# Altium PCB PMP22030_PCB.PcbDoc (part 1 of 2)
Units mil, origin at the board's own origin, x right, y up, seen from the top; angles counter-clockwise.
Board outline 4950 x 3450 mil, 4 copper layers (Top Layer, Signal Layer 1, Signal Layer 2, Bottom Layer), stack 55.6 mil thick; 125 components, 59 nets, 280 pads, 156 vias.
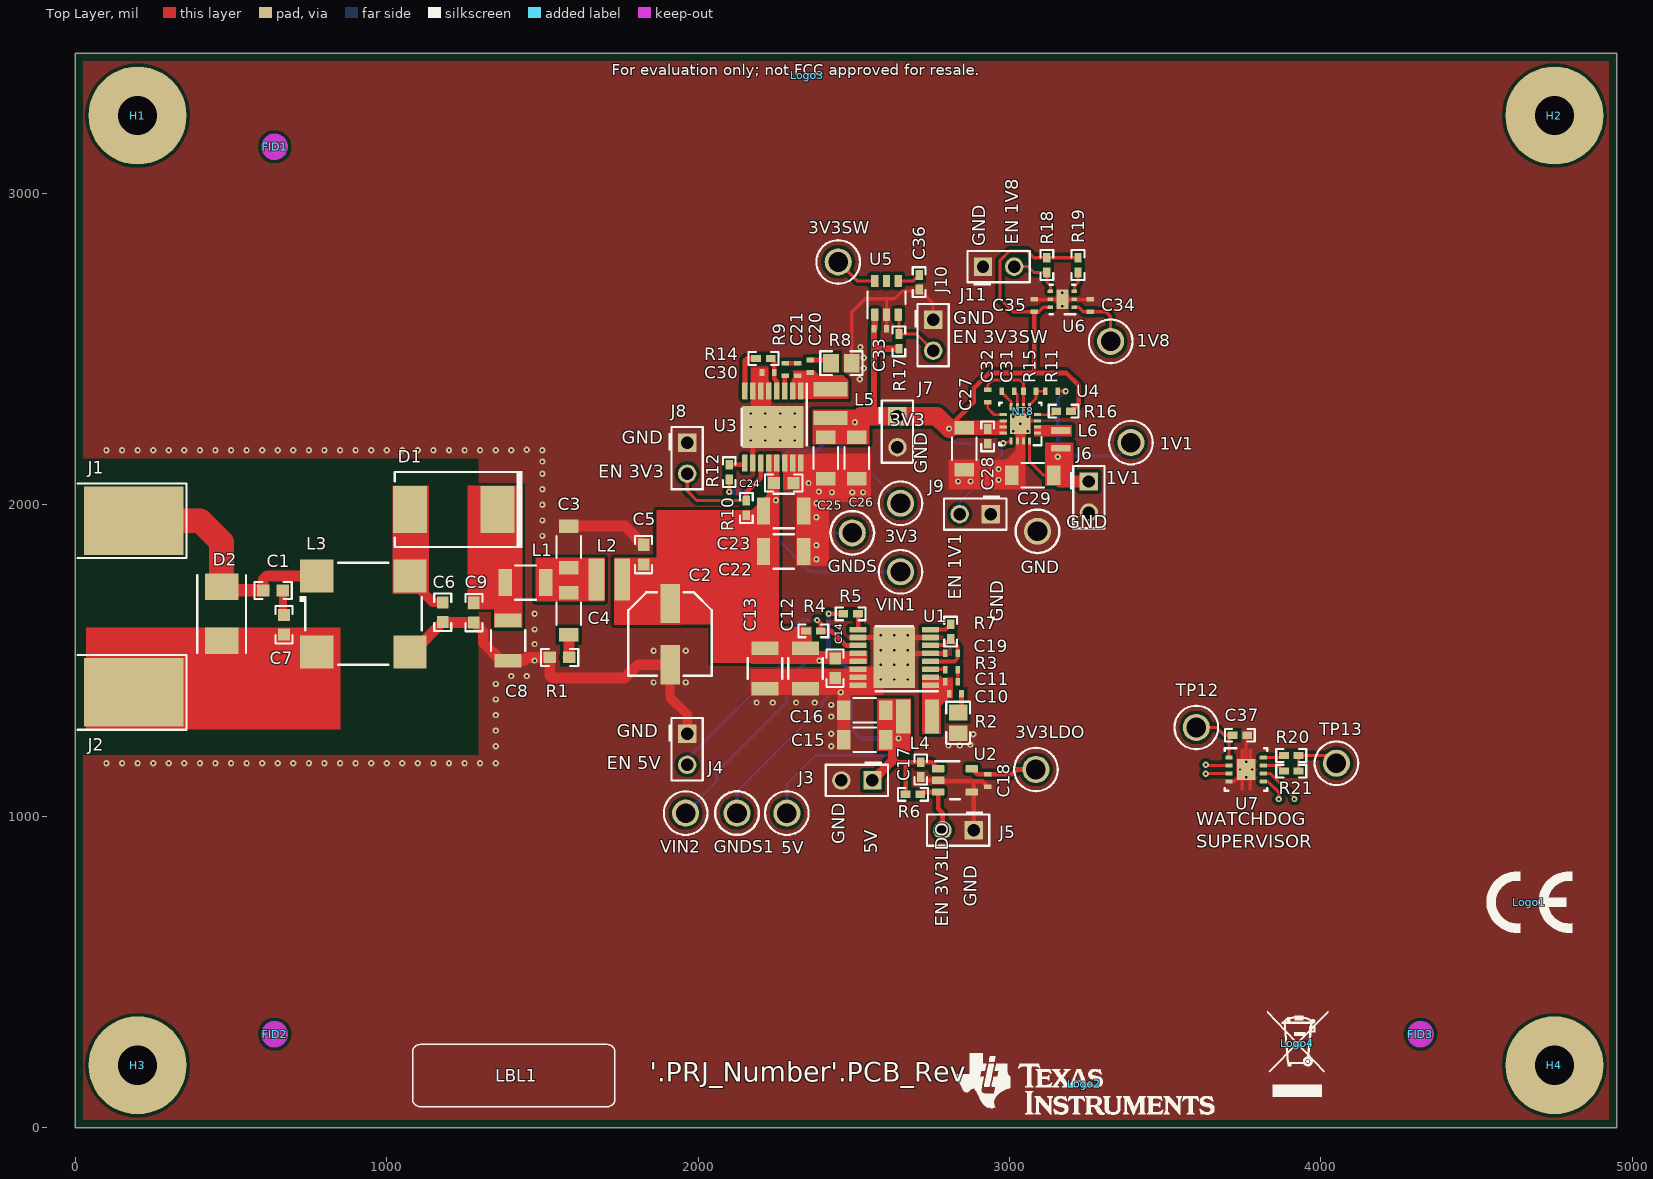
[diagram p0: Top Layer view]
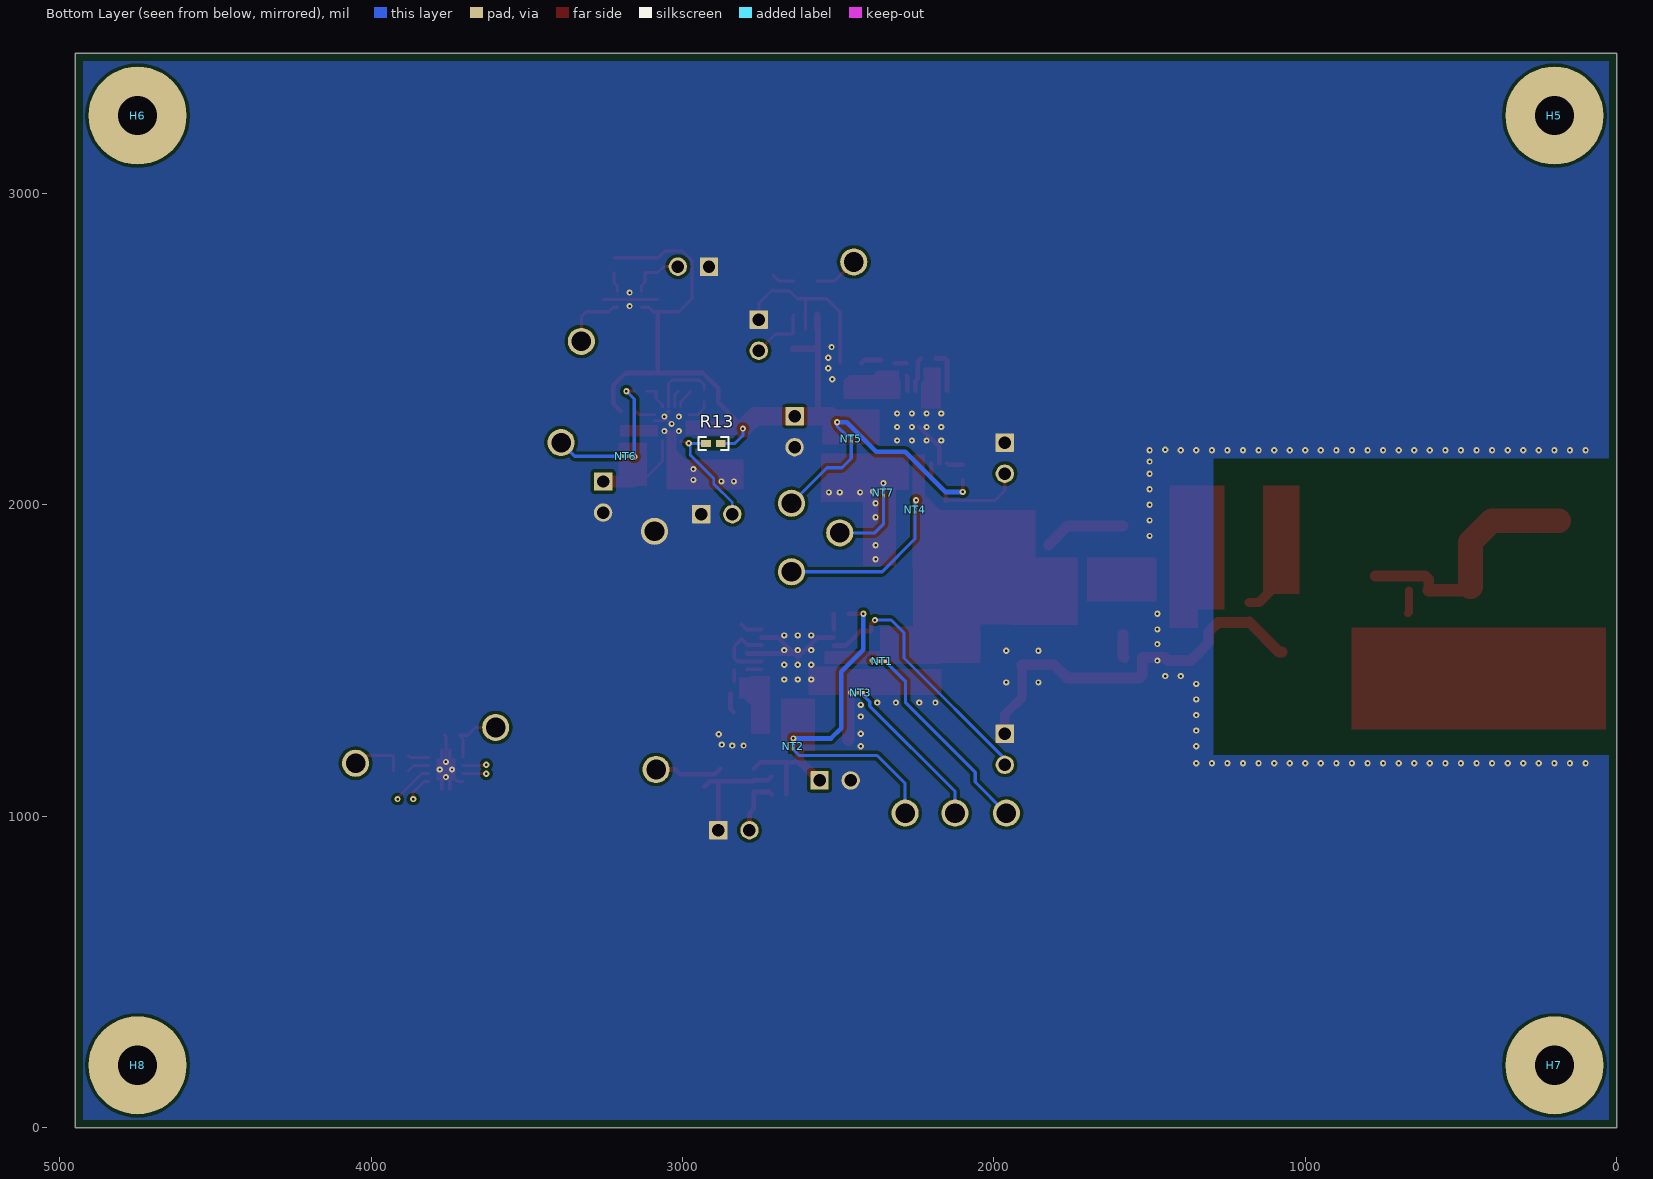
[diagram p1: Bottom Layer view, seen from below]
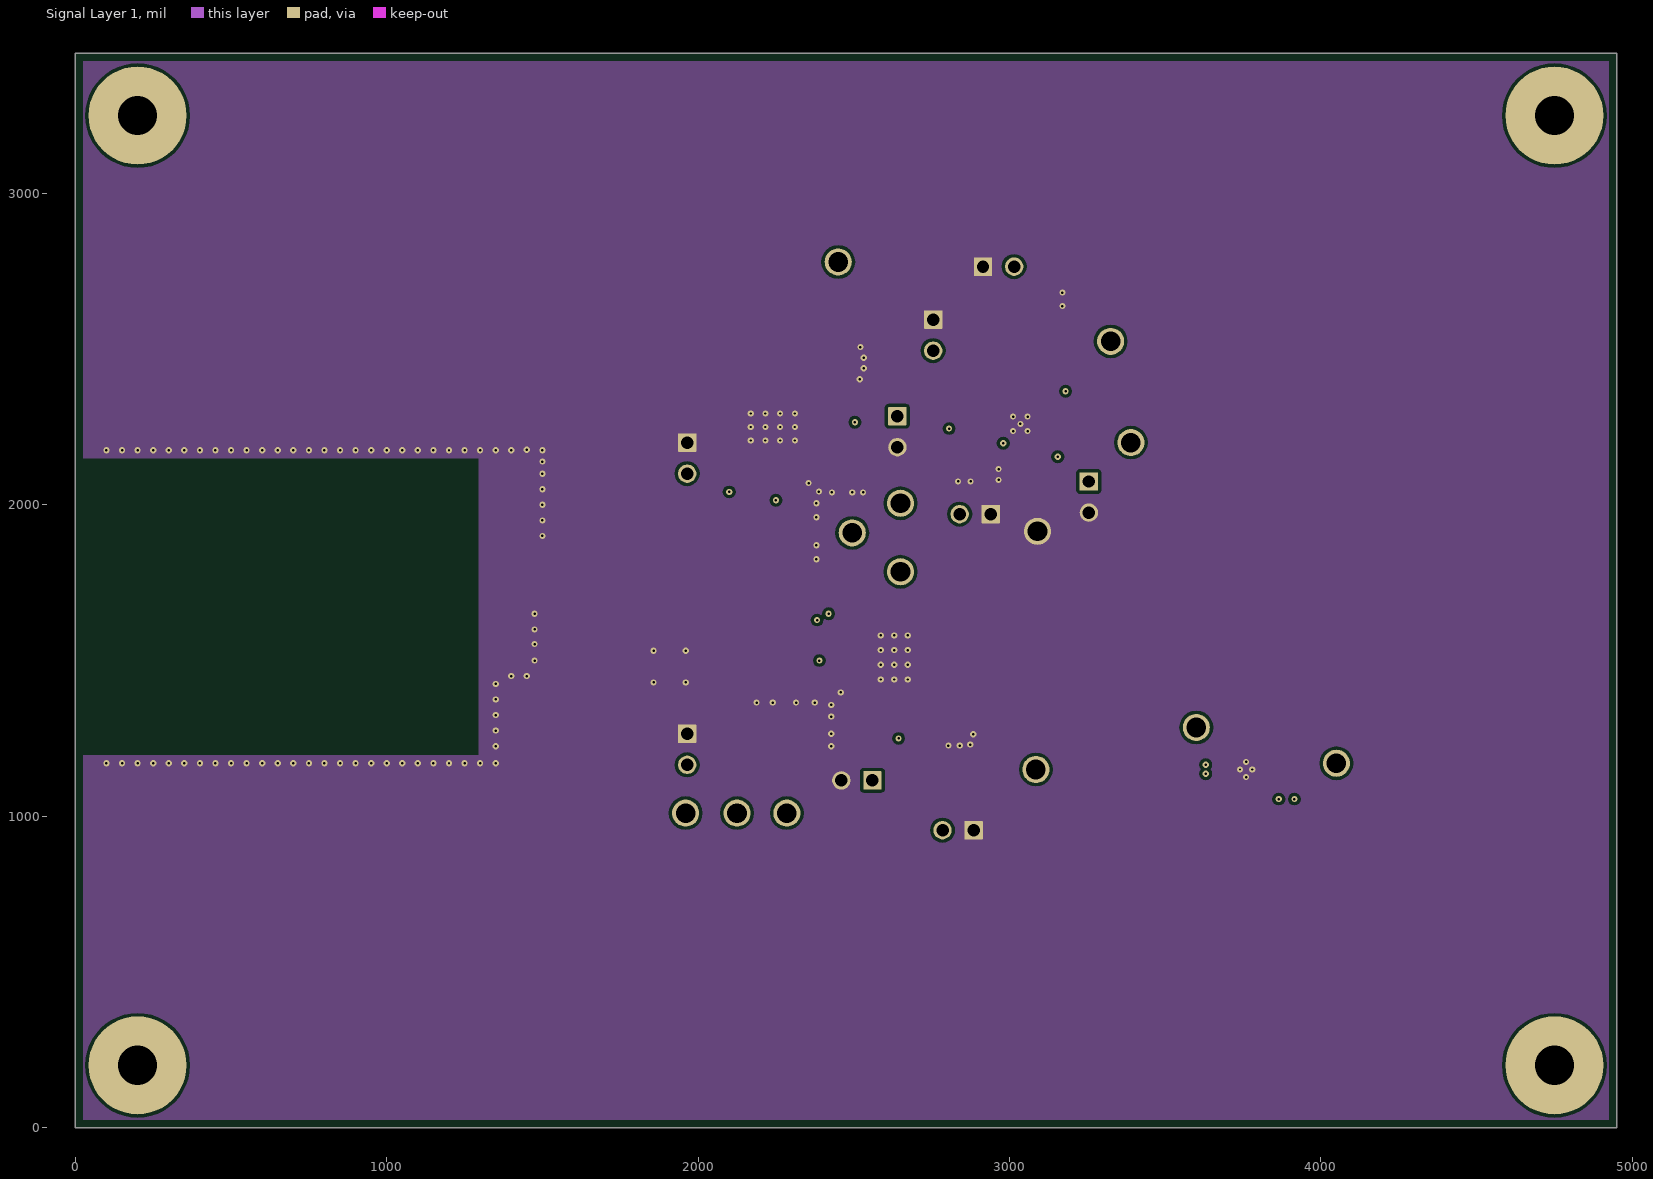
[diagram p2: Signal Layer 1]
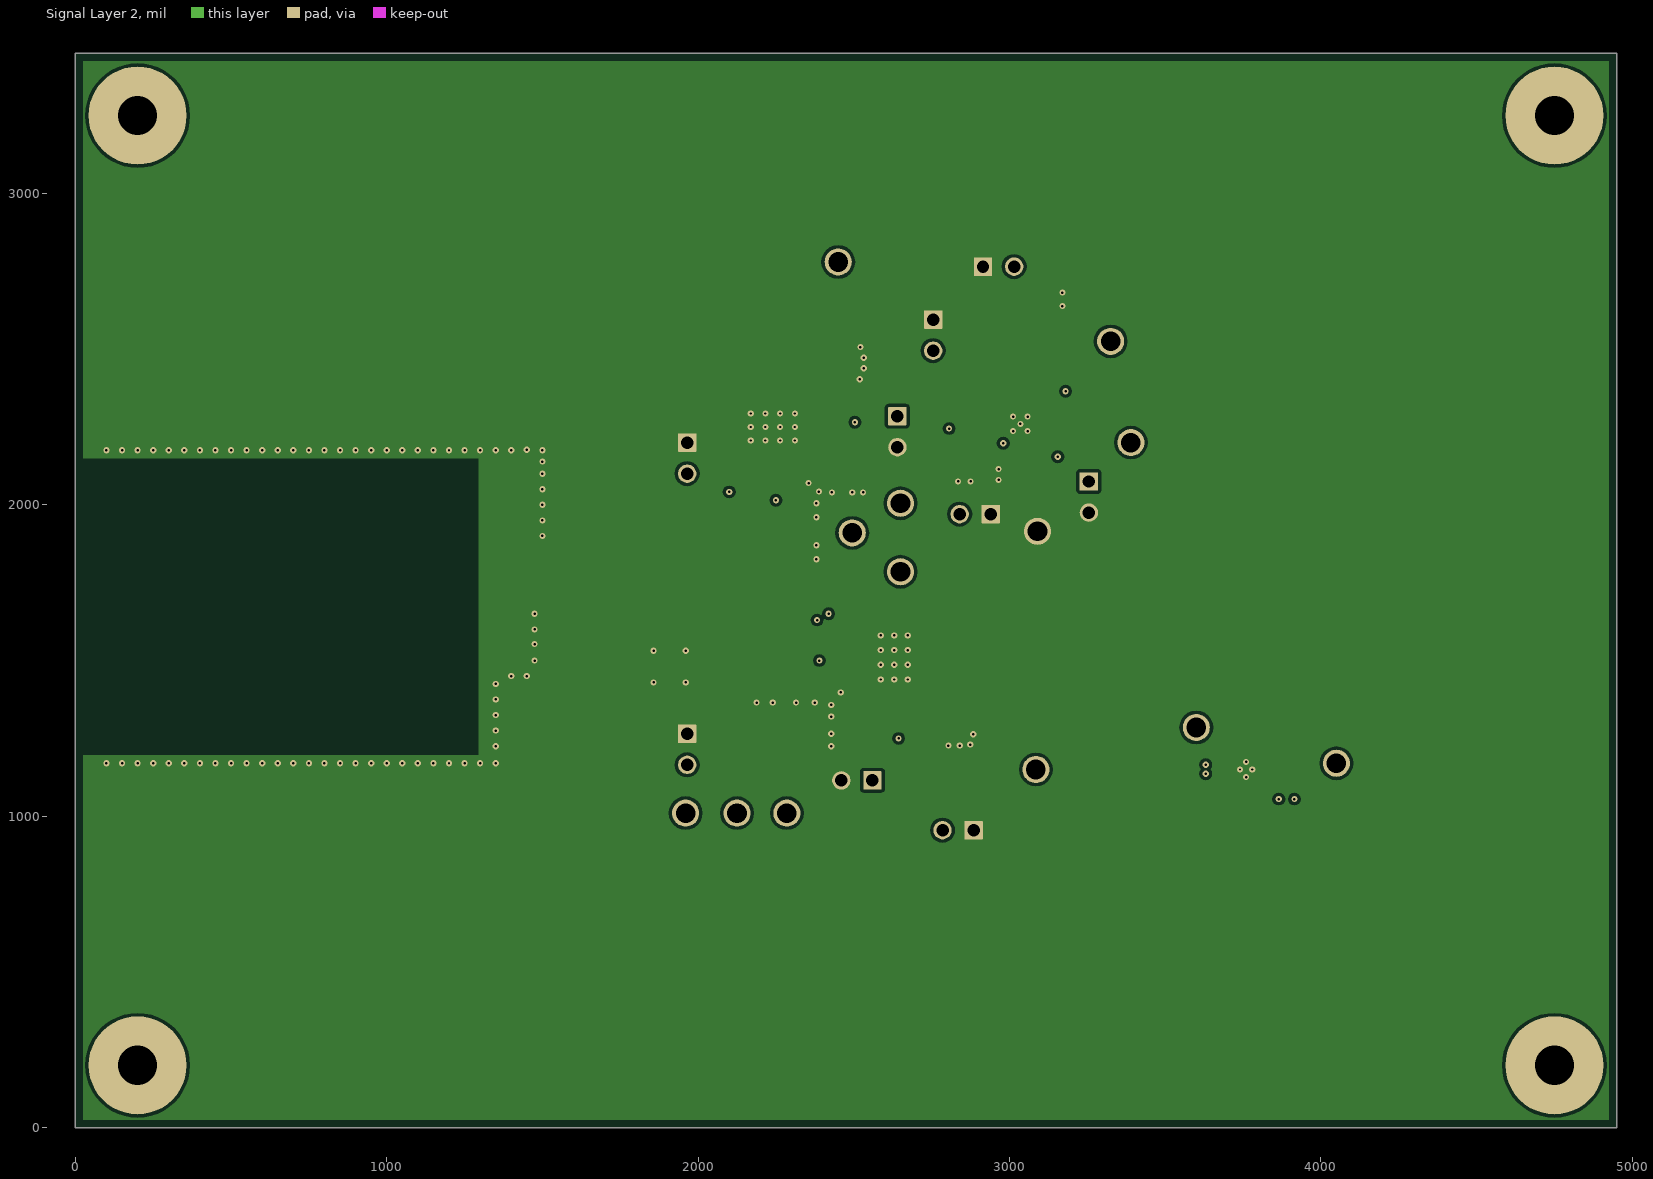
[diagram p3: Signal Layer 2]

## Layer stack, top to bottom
Top Solder: solder mask 0.4, Solder Resist, Dk 3.5
Top Layer: signal copper 1.4
Dielectric 2: prepreg 5, Dk 4.2
Signal Layer 1: signal copper 1.4
Dielectric1: core 40, FR-4, Dk 4.8
Signal Layer 2: signal copper 1.4
Dielectric 3: prepreg 5, Dk 4.2
Bottom Layer: signal copper 1.4
Bottom Solder: solder mask 0.4, Solder Resist, Dk 3.5

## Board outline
0,0 4950,0 4950,3450 0,3450

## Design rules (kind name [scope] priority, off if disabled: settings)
AcuteAngle [All] p1: minimum=4.50000000000000E+0001 checktracksonly=FALSE
AssemblyTestPointUsage [All] p1: valid=2
BoardOutlineClearance BoardOutlineClearance_MountingHoles [OnCopper and InComponentClass('Mounting Holes')] p1: gap=39.37 ignorepadtopadclearanceinfootprint=FALSE
BoardOutlineClearance BoardOutlineClearance_Poly [OnCopper and IsPoly] p2: gap=25 ignorepadtopadclearanceinfootprint=FALSE
BoardOutlineClearance [OnCopper and Not InComponentClass('Logo') and not InComponentClass('FiducialMark') and not InRegion(1000,500,4000,800) and not InPoly] p3: gap=75 ignorepadtopadclearanceinfootprint=FALSE
Clearance Clearance_Keepouts [((IsTrack Or IsArc) And Not InPoly) And IsFree and IsKeepOut vs ((IsTrack Or IsArc) And Not InPoly) And IsFree and IsKeepOut] p1: gap=0 ignorepadtopadclearanceinfootprint=FALSE
Clearance Clearance_Poly [InPolygon] p2: gap=10 ignorepadtopadclearanceinfootprint=TRUE
Clearance Clearance_FiducialMark [IsKeepOut and InComponentClass('FiducialMark') vs IsPad and InComponentClass('FiducialMark')] p3: gap=0 ignorepadtopadclearanceinfootprint=FALSE
Clearance [All] p4: gap=7.87 ignorepadtopadclearanceinfootprint=TRUE
ComponentClearance ComponentClearance_MountingHoles_FiducialMarks [InComponentClass('Mounting Holes') vs InComponentClass('FiducialMark')] p1: gap=50 collisioncheckmode=3 verticalgap=10 showdistances=FALSE
ComponentClearance ComponentClearance_Shunt [InComponentClass('Header') vs InComponentClass('Shunt')] p2: gap=0 collisioncheckmode=3 verticalgap=0 showdistances=FALSE
ComponentClearance ComponentClearance_Logo [InComponentClass('Logo')] p3: gap=50 collisioncheckmode=3 verticalgap=10 showdistances=FALSE
ComponentClearance ComponentClearance_ScrewToNut [(HasFootprint('NY PMS 440 0025 PH')) vs (HasFootprint('Keystone_1902C'))] p4: gap=5 collisioncheckmode=3 verticalgap=10 showdistances=FALSE
ComponentClearance ComponentClearance_MountingHoles [InComponentClass('Mounting Holes')] p5: gap=250 collisioncheckmode=3 verticalgap=100000 showdistances=FALSE
ComponentClearance ComponentClearance_SmallPassives [HasFootprint('0201*') or HasFootprint('0402*') or HasFootprint('0508') or HasFootprint('0603*') or HasFootprint('0612') or HasFootprint('0805*') or HasFootprint('0815*') or HasFootprint('0830*') or HasFootprint('1206*') or HasFootprint('1210*') or HasFootprint('1808*') or HasFootprint('1812*') or HasFootprint('1825*') or HasFootprint('2010*') or HasFootprint('2220*') or HasFootprint('2225*') or HasFootprint('2512*') or HasFootprint('2728*') or HasFootprint('3518*') vs HasFootprint('0201*') or HasFootprint('0402*') or HasFootprint('0508') or HasFootprint('0603*') or HasFootprint('0612') or HasFootprint('0805*') or HasFootprint('0815*') or HasFootprint('0830*') or HasFootprint('1206*') or HasFootprint('1210*') or HasFootprint('1808*') or HasFootprint('1812*') or HasFootprint('1825*') or HasFootprint('2010*') or HasFootprint('2220*') or HasFootprint('2225*') or HasFootprint('2512*') or HasFootprint('2728*') or HasFootprint('3518*')] p6: gap=14.96 collisioncheckmode=3 verticalgap=10 showdistances=FALSE
ComponentClearance ComponentClearance_THtoSMT [IsThruComponent vs IsSMTComponent] p7: gap=40 collisioncheckmode=3 verticalgap=30 showdistances=FALSE
ComponentClearance ComponentClearance_THtoTH [IsThruComponent vs IsThruComponent] p8: gap=30 collisioncheckmode=3 verticalgap=30 showdistances=FALSE
ComponentClearance [All] p9: gap=30 collisioncheckmode=3 verticalgap=10 showdistances=FALSE
DiffPairsRouting [All] p1: maxlimit=100 minlimit=10 mostfreqgap=10 toplayer_minwidth=15 toplayer_maxwidth=15 toplayer_prefwidth=15 midlayer1_minwidth=15 midlayer1_maxwidth=15 midlayer1_prefwidth=15 midlayer2_minwidth=15 midlayer2_maxwidth=15 midlayer2_prefwidth=15 bottomlayer_minwidth=15 bottomlayer_maxwidth=15 bottomlayer_prefwidth=15 maxuncoupledlength=1000
FabricationTestPointUsage TestPointUsage [All] p1: valid=2 allowmultiple=FALSE
FabricationTestpoint Testpoint [All] p1: side=3 testpointundercomponent=TRUE minsize=40 maxsize=100 preferedsize=60 minholesize=0 maxholesize=40 preferedholesize=32 testpointgrid=1 allowsidetop=TRUE allowsidebottom=TRUE usegrid=TRUE gridtolerance=0.01
FanoutControl Fanout_LCC [IsLCC] p1: bgadir=Out bgaviamode=Centered fanoutstyle=Auto fanoutdirection=Alternating viagrid=1 // Fanout_LCC (Default Rule)
FanoutControl Fanout_BGA [IsBGA] p2: bgadir=Out bgaviamode=Centered fanoutstyle=Auto fanoutdirection=Alternating viagrid=1 // Fanout_BGA (Default Rule)
FanoutControl Fanout_Default [All] p4: bgadir=Out bgaviamode=Centered fanoutstyle=Auto fanoutdirection=Alternating viagrid=1 // Fanout_Default (Default Rule)
FanoutControl Fanout_Small [(CompPinCount < 5)] p5: bgadir=Out bgaviamode=Centered fanoutstyle=Auto fanoutdirection=OutThenIn viagrid=1 // Fanout_Small (Default Rule)
HoleSize [All] p1: absolutevalues=TRUE maxlimit=251 minlimit=7.87 maxpercent=80.000 minpercent=20.000
MinimumAnnularRing MinimumAnnularRing_ThermalPadVias [IsVia and InAnyComponent] p1: minimumring=5.91
MinimumAnnularRing [All] p2: minimumring=6
MinimumSolderMaskSliver MinimumSolderMaskSliver_Logo [InComponentClass('Logo') vs InComponentClass('Logo')] p1: minsoldermaskwidth=0.7
MinimumSolderMaskSliver [All] p2: minsoldermaskwidth=3.94
PlaneConnect [All] p1: planeconnectstyle=Relief reliefexpansion=10 reliefentries=4 reliefconductorwidth=10 reliefairgap=10
PolygonConnect [All] p1: connectstyle=Direct reliefconductorwidth=10 reliefentries=4 polygonreliefangle="90 Angle" airgapwidth=10
RoutingVias ThermalPadVias [IsVia and InAnyComponent] p1: holewidth=7.87 width=19.68 viastyle="Through Hole" minholewidth=7.87 minwidth=19.68 maxholewidth=12.99 maxwidth=23.62
RoutingVias [All] p2: holewidth=16 width=34 viastyle="Through Hole" minholewidth=7.87 minwidth=20 maxholewidth=40 maxwidth=65
SilkToBoardRegionClearance [Not ((IsComment or IsDesignator) And (Hide <> 'False')) and not InRegion(1000,500,4000,800)] p1:
SilkToSilkClearance SilkToSilkClearance_Pb-FreeLogo [(HasFootprint('Pb-Free_Overlay_Medium') OR HasFootprint('Pb-Free_Overlay_Small')) vs (HasFootprint('Pb-Free_Overlay_Medium') OR HasFootprint('Pb-Free_Overlay_Small'))] p1: silktosilkclearance=0
SilkToSilkClearance [All] p2: silktosilkclearance=3.94
SilkToSolderMaskClearance SilkToComponentPadClearance [(IsPad or IsFill or IsRegion) and InAnycomponent] p1: minsilkscreentomaskgap=5 clearancetoexposedcopper=TRUE
SilkToSolderMaskClearance "Silk to Solder Mask Opening" [All] p2: minsilkscreentomaskgap=3.94 clearancetoexposedcopper=FALSE
SolderMaskExpansion [All] p1: expansion=1.97
UnRoutedNet [All] p1: checkbadconnections=TRUE
Width [All] p1: maxlimit=100 minlimit=6 preferedwidth=10 checkconnectedcopper=TRUE
14 further rules are at their usual default settings.

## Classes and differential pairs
component class PMP22030_5V: 3V3LDO 5V C1 C2 C3 C4 C5 C6 C7 C8 C9 C10 C11 C12 C13 C14 C15 C16 C17 C18 C19 D1 D2 GNDS1 J1 J2 J3 J4 J5 L1 L2 L3 L4 NT1 NT2 NT3 R1 R2 R3 R4 R5 R6 R7 U1 U2 VIN2
component class PMP22030_3V3: 1V1 1V8 3V3 3V3SW C20 C21 C22 C23 C24 C25 C26 C27 C28 C29 C30 C31 C32 C33 C34 C35 C36 C37 GND GNDS J6 J7 J8 J9 J10 J11 L5 L6 NT4 NT5 NT6 NT7 NT8 R8 R9 R10 R11 R12 R13 R14 R15 R16 R17 R18 R19 R20 R21 TP12 TP13 U3 U4 U5 U6 U7 VIN1
component class Header: J3 J4 J5 J6 J7 J8 J9 J10 J11
component class "Mounting Holes": H1 H2 H3 H4
component class Logo: Logo2
component class PMP22030_Hardware: FID1 FID2 FID3 H1 H2 H3 H4 H5 H6 H7 H8 LBL1 Logo1 Logo2 Logo3 Logo4 ZZ1 ZZ2 ZZ3 ZZ4
component class FiducialMark: FID1 FID2 FID3
component class AssemblyNote: ZZ1 ZZ2 ZZ3 ZZ4
component class Label: LBL1

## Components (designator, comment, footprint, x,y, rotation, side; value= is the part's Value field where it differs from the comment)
1V1 "5129" Keystone5129 3390,2200 r180 top
1V8 "5129" Keystone5129 3325,2525 r180 top
3V3 "5129" Keystone5129 2650,2005 r90 top
3V3LDO "5129" Keystone5129 3085,1150 r0 top
3V3SW "5129" Keystone5129 2450,2780 r90 top
5V "5129" Keystone5129 2285,1010 r90 top
C1 "C0603C102J5RACAUTO" 0603 635,1725 r0 top value=1000pF
C2 "EEEFT1H470AP" Panasonic_D 1910,1585 r270 top value=47uF
C3 "Cf1" 1206_180 1585,1865 r90 top value=1uF
C4 "Cd" 1206_180 1585,1650 r270 top value=4.7uF
C5 "GRM188R71H104KA93D" 0603 1825,1840 r90 top value=0.1uF
C6 "C0603C102J5RACAUTO" 0603 1180,1655 r90 top value=1000pF
C7 "C0603C102J5RACAUTO" 0603 670,1615 r90 top value=1000pF
C8 "Cf2" 1210_280 1390,1565 r270 top value=4.7uF
C9 "GRM188R71H104KA93D" 0603 1280,1654 r270 top value=0.1uF
C10 "GCM155R71H391KA37D" 0402S 2826.18,1392.64 r180 top value=390pF
C11 "C1005X7R1C224K050BC" 0402S 2813.99,1431.64 r180 top value=0.22uF
C12 "CGA6P3X7R1H475K250AB" 1210_280 2345,1475 r270 top value=4.7uF
C13 "CGA6P3X7R1H475K250AB" 1210_280 2215,1475.04 r270 top value=4.7uF
C14 "CINHF" 0603 2440,1475 r270 top value=0.1uF
C15 "GCM31CR71A226KE02" 1206_180 2535,1245 r180 top value=22uF
C16 "GCM31CR71A226KE02" 1206_180 2535,1340 r180 top value=22uF
C17 "GCM155R71A104KA55D" 0402 2715,1150 r270 top value=0.1uF
C18 "GCM155C71A105KE38D" 0402_070 2930,1115 r270 top value=1uF
C19 "GCM155C71A105KE38D" 0402_070 2813.99,1523.64 r180 top value=1uF
C20 "GCM155R71H391KA37D" 0402S 2360,2445 r270 top value=390pF
C21 "C1005X7R1C224K050BC" 0402S 2320,2435 r270 top value=0.22uF
C22 "CGA6P3X7R1H475K250AB" 1210_280 2275,1850 r0 top value=4.7uF
C23 "CGA6P3X7R1H475K250AB" 1210_280 2275,1980 r0 top value=4.7uF
C24 "CINHF" 0603 2275,2070 r0 top value=0.1uF
C25 "GCM31CR71A226KE02" 1206_180 2410,2150 r270 top value=22uF
C26 "GCM31CR71A226KE02" 1206_180 2510,2150 r270 top value=22uF
C27 "GCM31CR71A226KE02" 1206_180 2855,2180 r270 top value=22uF
C28 "GCM155R71A104KA55D" 0402 2930,2220 r270 top value=0.1uF
C29 "GCM31CR71A226KE02" 1206_180 3075,2095 r180 top value=22uF
C30 "GCM155C71A105KE38D" 0402_070 2225,2425 r180 top value=1uF
C31 "GRM155R71C103KA01D" 0402S 2995,2365 r180 top value=0.01uF
C32 "GRM155R71C103KA01D" 0402S 2930,2350 r90 top value=0.01uF
C33 "GCM155C71A105KE38D" 0402_070 2585,2565 r0 top value=1uF
C34 "GCM155C71A105KE38D" 0402_070 3260,2640 r90 top value=1uF
C35 "GCM155C71A105KE38D" 0402_070 3080,2640 r90 top value=1uF
C36 "GCM155R71H391KA37D" 0402 2710,2715 r90 top value=390pF
C37 "GCM155R71A104KA55D" 0402 3740,1260 r0 top value=0.1uF
D1 "SL44HE3_A/H" SMC 1215,1985 r180 top value=40V
D2 "SM6T42CAY" SMB-Bi 470,1650 r90 top value=36V
FID1 "Fiducial" Fiducial10-20 640,3150 r0 top
FID2 "Fiducial" Fiducial10-20 640,300 r0 top
FID3 "Fiducial" Fiducial10-20 4320,300 r0 top
GND "5011" Keystone5011 3090,1915 r180 top
GNDS "5011" Keystone5011 2495,1910 r90 top
GNDS1 "5011" Keystone5011 2125,1010 r90 top
H1 "NY PMS 440 0025 PH" "NY PMS 440 0025 PH" 200,3250 r0 top locked
H2 "NY PMS 440 0025 PH" "NY PMS 440 0025 PH" 4750,3250 r0 top locked
H3 "NY PMS 440 0025 PH" "NY PMS 440 0025 PH" 200,200 r0 top locked
H4 "NY PMS 440 0025 PH" "NY PMS 440 0025 PH" 4750,200 r0 top locked
H5 "1902C" Keystone_1902C 200,3250 r180 bottom locked
H6 "1902C" Keystone_1902C 4750,3250 r180 bottom locked
H7 "1902C" Keystone_1902C 200,200 r180 bottom locked
H8 "1902C" Keystone_1902C 4750,200 r180 bottom locked
J1 "6091" 6091 2.01,1948.82 r0 top
J2 "6092" 6092 2.01,1397.64 r0 top
J3 "PEC02SAAN" CONN_PEC02SAAN 2510,1115 r180 top
J4 "PEC02SAAN" CONN_PEC02SAAN 1965,1215 r270 top
J5 "PEC02SAAN" CONN_PEC02SAAN 2835,955 r180 top
J6 "PEC02SAAN" CONN_PEC02SAAN 3255,2025 r270 top
J7 "PEC02SAAN" CONN_PEC02SAAN 2640,2235 r270 top
J8 "PEC02SAAN" CONN_PEC02SAAN 1965,2150 r270 top
J9 "PEC02SAAN" CONN_PEC02SAAN 2890,1970 r180 top
J10 "PEC02SAAN" CONN_PEC02SAAN 2755,2545 r270 top
J11 "PEC02SAAN" CONN_PEC02SAAN 2965,2765 r0 top
L1 "Lf1" 1210_280 1445,1750 r0 top value="600 ohm"
L2 "78438336022" FP-78438336022_SMD2-MFG 1715,1760 r0 top
L3 "744273102" WE-SL5_HC 925,1650 r0 top value=11uH
L4 "VCTA32251B-3R3MS6" VCTA32251B 2705,1320 r180 top value=3.3uH
L5 "VCTA32251B-1R5MS6" VCTA32251B 2425,2325 r270 top value=1.5uH
L6 "DFE201612E-R47M=P2" DFE201612E 3165,2210 r270 top value=470nH
LBL1 "THT-14-423-10" Label_650x200 1408,167 r0 top
Logo1 "CE Mark" CE_Mark_5mm 4670,724 r0 top
Logo2 "Texas Instruments" TI_Stacked_Overlay_Small 3240,140 r0 top
Logo3 "FCC disclaimer" FCC_disclaimer 2350,3380 r0 top
Logo4 "WEEE logo" WEEE_Minimum 3924,271 r0 top
NT1 "Net-Tie" Net-Tie_10mil 2359.09,1497.64 r180 bottom net-tie
NT2 "Net-Tie" Net-Tie_10mil 2645,1225 r270 bottom net-tie
NT3 "Net-Tie" Net-Tie_10mil 2427.99,1396.64 r0 bottom net-tie
NT4 "Net-Tie" Net-Tie_10mil 2253.35,1985 r270 bottom net-tie
NT5 "Net-Tie" Net-Tie_10mil 2458,2213 r270 bottom net-tie
NT6 "Net-Tie" Net-Tie_10mil 3181.68,2156 r0 bottom net-tie
NT7 "Net-Tie" Net-Tie_10mil 2355,2039.21 r90 bottom net-tie
NT8 "Net-Tie" Net-Tie_10mil 3045,2300 r90 top net-tie
R1 "Rd" 0603 1555,1510 r0 top value=0.51
R2 "ERJ-6GEYJ3R0V" 0805 2835,1300 r90 top value=3.0
R3 "CRCW04020000Z0EDHP" 0402S 2813.89,1470.64 r180 top value=0
R4 "RMCF0402FT100K" 0402 2370,1595 r0 top value=100k
R5 "CRCW04020000Z0EDHP" 0402 2490,1650 r0 top value=0
R6 "RMCF0402FT100K" 0402 2690,1070 r0 top value=100k
R7 "RMCF0402FT100K" 0402 2810.99,1592.64 r90 top value=100k
R8 "ERJ-6GEYJ3R0V" 0805 2460,2455 r180 top value=3.0
R9 "CRCW04020000Z0EDHP" 0402S 2280,2435 r270 top value=0
R10 "RMCF0402FT100K" 0402 2155,1990 r90 top value=100k
R11 "CRCW040237K4FKED" 0402S 3135,2365 r0 top value=37.4k
R12 "CRCW04020000Z0EDHP" 0402 2100,2105 r90 top value=0
R13 "RMCF0402FT100K" 0402 2900.68,2197 r0 bottom value=100k
R14 "RMCF0402FT100K" 0402 2210,2470 r180 top value=100k
R15 "CRCW0402100KFKED" 0402S 3065,2365 r0 top value=100k
R16 "RMCF0402FT100K" 0402 3174.06,2301 r0 top value=100k
R17 "RMCF0402FT100K" 0402 2645,2525 r90 top value=100k
R18 "RMCF0402FT100K" 0402 3120,2770 r270 top value=100k
R19 "RMCF0402FT100K" 0402 3220,2770 r90 top value=100k
R20 "RMCF0402FT100K" 0402 3905,1195 r0 top value=100k
R21 "RMCF0402FT100K" 0402 3905,1145 r0 top value=100k
TP12 "5129" Keystone5129 3600,1285 r0 top
TP13 "5129" Keystone5129 4050,1170 r0 top
U1 "LM63615DQPWPRQ1" PWP0016K_N 2630,1510 r180 top
U2 "TLV73333PQDBVRQ1" DBV0005A_N 2825,1115 r0 top
U3 "LM63625DQPWPTQ1" PWP0016K_N 2240,2250 r270 top
U4 "TPS62090RGTR" RGT0016C 3035,2260 r180 top
U5 "TPS22918TDBVRQ1" DBV0006A_N 2605,2665 r90 top
U6 "LP5912Q1.8DRVRQ1" DRV0006A 3170,2660 r180 top
U7 "TPS3851G18EDRBR" DRB0008A 3760,1150 r0 top
VIN1 "5129" Keystone5129 2650,1785 r90 top
VIN2 "5129" Keystone5129 1960,1010 r90 top
ZZ1 "This Assembly Note is for PCB labels only" AssemblyNoteLabel 185,3938 r0 top
ZZ2 "These assemblies are ESD sensitive, ESD precautions shall be observed." AssemblyNote 185,3829.11 r0 top
ZZ3 "These assemblies must be clean and free from flux and all contaminants. Use of no clean flux is not acceptable." AssemblyNote 185,3740.56 r0 top
ZZ4 "These assemblies must comply with workmanship standards IPC-A-610 Class 2, unless otherwise specified." AssemblyNote 185,3652 r0 top

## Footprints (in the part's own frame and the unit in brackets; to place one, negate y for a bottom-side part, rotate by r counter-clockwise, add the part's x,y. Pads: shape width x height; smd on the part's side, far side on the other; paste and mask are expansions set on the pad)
0402 [mm] "0402 from SM-752 data"
  rect 0.8x0.6 smd: 1(-0.6,0) 2(0.6,0)
  silkscreen extent -1.22,-0.52 1.22,0.52, body extent -0.55,-0.3 0.55,0.3, height 0.6
0402_070 [mil] "SMD, 2-Leads, Body 1.2x0.7mm, Height 0.7mm"
  rect 15x24 smd: 1(-20,0) 2(20,0)
  body extent -24,-14 24,14, height 28
0402S [mil] "Based on C0402S footprint from PADS legacy"
  rect 15x24 smd: 1(-20,0) 2(20,0)
  body extent -22,-12 22,12, height 24
0603 [mm] "0603 from SM-752 data"
  rect 1x0.95 smd: 1(-0.8,0) 2(0.8,0)
  silkscreen extent -1.52,-0.69 1.52,0.69, body extent -0.87,-0.47 0.87,0.47, height 1
0805 [mm] "0805 from SM-752 data"
  rect 1.3x1.5 smd: 1(-0.85,0) 2(0.85,0)
  silkscreen extent -1.72,-0.97 1.72,0.97, body extent -1.1,-0.72 1.1,0.72, height 1.45
1206_180 [mm] "1206_180"
  rect 1.1x1.6 smd: 1(-1.7,0) 2(1.7,0)
  silkscreen extent -0.9,-1 0.9,1, body extent -1.75,-0.95 1.75,0.95, height 1.8
1210_280 [mm] "SMD, 2-Leads, Body 3.6x2.8mm, Height 2.8mm"
  rect 1.1x2.2 smd: 1(-1.65,0) 2(1.65,0)
  silkscreen extent -0.84,-1.4 0.84,1.4, body extent -1.8,-1.4 1.8,1.4, height 2.8
6091 [mil] "Keystone Insulated End Launch Banana Jack"
  rect 320x220 smd: 1(185,0)
  silkscreen extent 5,-120 355,120, body extent -666,-216 271,216, height 227
6092 [mil] "Keystone Insulated End Launch Banana Jack"
  rect 320x220 smd: 1(185,0)
  silkscreen extent 5,-120 355,120, body extent -666,-216 271,216, height 227
AssemblyNote [mil] "Assembly Note"
AssemblyNoteLabel [mil] "Assembly Note for PCB Labels"
CE_Mark_5mm [mil] "Minimum text height for CE Mark"
  silkscreen extent -138,-98 138,98
CONN_PEC02SAAN [mm] "SULLINS"
  rrect7% 1.5x1.5 hole 1.016: 1(-1.27,0)
  round 1.5 hole 1.016: 2(1.27,0)
  silkscreen extent -2.54,-1.52 2.54,1.27, body extent -2.54,-1.27 2.54,1.27, height 8.38
DBV0005A_N [mm] "SOT23, 5-Leads, Body 2.9x1.6mm, Pitch 0.95mm, Lead Span 2.8mm, IPC Medium Density"
  rrect17% 1x0.6 smd: 1(-1.375,0.95) 2(-1.375,0) 3(-1.375,-0.95) 4(1.375,-0.95) 5(1.375,0.95)
  silkscreen extent -1.63,-1.55 0.38,1.55, body extent -1.42,-1.46 1.42,1.46, height 1.09
DBV0006A_N [mm] "SOT23, 6-Leads, Body 2.9x1.6mm, Pitch 0.95mm, Lead Span 2.8mm, IPC Medium Density"
  rrect17% 1x0.6 smd: 1(-1.375,0.95) 2(-1.375,0) 3(-1.375,-0.95) 4(1.375,-0.95) 5(1.375,0) 6(1.375,0.95)
  silkscreen extent -1.68,-1.55 0.5,1.55, body extent -1.42,-1.46 1.42,1.46, height 1.12
DFE201612E [mm] "MuRata recommended"
  rrect18% 0.55x1.6 smd: 1(-0.725,0) 2(0.725,0)
  body extent -1.1,-0.9 1.1,0.9, height 1.2
DRB0008A [mm] "VSON-8"
  rrect32% 0.6x0.31 smd: 1(-1.4,0.975) 2(-1.4,0.325) 3(-1.4,-0.325) 4(-1.4,-0.975) 5(1.4,-0.975) 6(1.4,-0.325) 7(1.4,0.325) 8(1.4,0.975)
  rrect7% 1.5x1.75 smd paste-0.75: 9(0,0)
  Top Layer region: -0.7,-0.875 -0.49,-0.875 -0.471,-0.879 -0.455,-0.89 -0.444,-0.906 -0.44,-0.925 -0.44,-0.925 -0.44,-1.65 -0.436,-1.669 -0.425,-1.685 -0.409,-1.696 -0.39,-1.7 -0.39,-1.7 -0.26,-1.7 -0.241,-1.696 -0.225,-1.685 -0.214,-1.669 -0.21,-1.65 -0.21,-1.65 -0.21,-0.925 -0.206,-0.906 -0.195,-0.89 -0.179,-0.879 -0.16,-0.875 -0.16,-0.875 0.16,-0.875 0.179,-0.879 0.195,-0.89 0.206,-0.906 0.21,-0.925 0.21,-0.925 0.21,-1.65 0.21,-1.65 0.214,-1.669 0.225,-1.685 0.241,-1.696 0.26,-1.7 0.26,-1.7 0.39,-1.7 0.409,-1.696 0.425,-1.685 0.436,-1.669 0.44,-1.65 0.44,-1.65 0.44,-0.925 0.444,-0.906 0.455,-0.89 0.471,-0.879 0.49,-0.875 0.49,-0.875 0.7,-0.875 0.719,-0.871 0.735,-0.86 0.746,-0.844 0.75,-0.825 0.75,-0.825 0.75,0.825 0.746,0.844 0.735,0.86 0.719,0.871 0.7,0.875 0.7,0.875 0.49,0.875 0.471,0.879 0.455,0.89 0.444,0.906 0.44,0.925 0.44,0.925 0.44,1.65 0.436,1.669 0.425,1.685 0.409,1.696 0.39,1.7 0.39,1.7 0.26,1.7 0.241,1.696 0.225,1.685 0.214,1.669 0.21,1.65 0.21,1.65 0.21,1.65 0.21,0.925 0.206,0.906 0.195,0.89 0.179,0.879 0.16,0.875 0.16,0.875 -0.16,0.875 -0.179,0.879 -0.195,0.89 -0.206,0.906 -0.21,0.925 -0.21,0.925 -0.21,1.65 -0.214,1.669 -0.225,1.685 -0.241,1.696 -0.26,1.7 -0.26,1.7 -0.39,1.7 -0.409,1.696 -0.425,1.685 -0.436,1.669 -0.44,1.65 -0.44,1.65 -0.44,0.925 -0.444,0.906 -0.455,0.89 -0.471,0.879 -0.49,0.875 -0.49,0.875 -0.7,0.875 -0.719,0.871 -0.735,0.86 -0.746,0.844 -0.75,0.825 -0.75,0.825 -0.75,-0.825 -0.746,-0.844 -0.735,-0.86 -0.719,-0.871 -0.7,-0.875
  silkscreen extent -1.73,-1.73 1.73,1.73, body extent -1.5,-1.5 1.5,1.5, height 0.77
DRV0006A [mm] "SON, 6-Leads, Body 2x2mm, Pitch 0.65mm, Thermal Pad 1.6x1mm, TI Recommended"
  rrect33% 0.45x0.3 smd: 1(-0.975,0.65) 2(-0.975,0) 3(-0.975,-0.65) 4(0.975,-0.65) 5(0.975,0) 6(0.975,0.65)
  rrect14% 1x0.7 on Top Paste: 7(0,0.45) 7(0,-0.45)
  rrect10% 1x1.6 smd paste-0.5: 7(0,0)
  silkscreen extent -1.05,-1.2 1.05,1.2, body extent -1.05,-1.05 1.05,1.05, height 0.81
FCC_disclaimer [mil]
Fiducial10-20 [mm]
  round 1 smd mask+0.5: 1(0,0)
  Top Layer keep-out circle w1.178: c0,0 r0.5
FP-78438336022_SMD2-MFG [mm]
  rrect8% 1.3x3.4 smd paste+0 mask+0: 1(-1.05,0) 2(1.05,0)
  body extent -1.8,-1.8 1.8,1.8, height 0.25
Keystone5011 [mil] "Keystone Multipurpose loops"
  round 87 hole 63: 1(0,0)
  silkscreen extent -70,-70 70,70, body extent -63,-63 63,62, height 319
Keystone5129 [mil] "Keystone Multipurpose loops"
  round 87 hole 63: 1(0,0)
  silkscreen extent -70,-70 70,70, body extent -63,-63 63,62, height 319
Keystone_1902C [mil] "Hex Standoff, 4-40 threaded, nylon"
  round 1 on Mech4: 0(0,0)
  body extent -145,-126 146,126, height 501
Label_650x200 [mil] "Thermal Transfer Label"
  round 1 on Mech13: 0(0,0)
  silkscreen extent -325,-100 325,100, body extent -325,-100 325,100, height 1
Net-Tie_10mil [mil] "10mil net tie, no solder mask opening, no solder paste"
  rect 10x10 smd paste-5 mask-5: 1(-10,0) 2(10,0)
  Top Layer region: -6,5 6,5 6,-5 -6,-5
"NY PMS 440 0025 PH" [mm] "4-40 nylon screw and mounting hole"
  round 8 hole 3.2: 1(0,0)
  body extent -3.3,-3.3 3.3,3.3, height 2.69
Panasonic_D [mm] "SMD, 2-Leads, Dia 6.3mm"
  rect 3.2x1.6 smd: 1(-2.5,0) 2(2.5,0)
  silkscreen extent -3.4,-3.4 3.4,3.4, body extent -3.4,-3.4 3.4,3.4, height 6.11
PWP0016K_N [mm] "TSSOP-16"
  rrect22% 1.4x0.45 smd: 1(-2.95,2.275) 2(-2.95,1.625) 3(-2.95,0.975) 4(-2.95,0.325) 5(-2.95,-0.325) 6(-2.95,-0.975) 7(-2.95,-1.625) 8(-2.95,-2.275) 9(2.95,-2.275) 10(2.95,-1.625) 11(2.95,-0.975) 12(2.95,-0.325) 13(2.95,0.325) 14(2.95,0.975) 15(2.95,1.625) 16(2.95,2.275)
  rrect3% 3.4x5 smd paste-1.7 mask-1.7: 17(0,0)
  rrect4% 2.46x2.31 on Top Solder: 17(0,0)
  rrect4% 2.46x2.31 on Top Paste: 17(0,0)
  silkscreen extent -3.55,-2.55 1.5,2.75, body extent -3.21,-2.5 3.21,2.5, height 1
RGT0016C [mm] "QFN, 16-Leads, Body 3x3mm, Pitch 0.5mm, Thermal Pad 1.7x1.7mm, TI Recommended"
  rrect42% 0.6x0.24 smd: 1(-1.4,0.75) 2(-1.4,0.25) 3(-1.4,-0.25) 4(-1.4,-0.75) 9(1.4,-0.75) 10(1.4,-0.25) 11(1.4,0.25) 12(1.4,0.75)
  rrect42% 0.24x0.6 smd: 5(-0.75,-1.4) 6(-0.25,-1.4) 7(0.25,-1.4) 8(0.75,-1.4) 13(0.75,1.4) 14(0.25,1.4) 15(-0.25,1.4) 16(-0.75,1.4)
  rrect6% 1.55x1.55 on Top Paste: 17(0,0)
  rrect6% 1.68x1.68 smd paste-0.85: 17(0,0)
  silkscreen extent -1.72,-1.72 1.73,1.73, body extent -1.5,-1.5 1.5,1.5, height 1
SMB-Bi [mil] "Molded Diode, 2-Leads, Body 5.4x3.6mm, IPC Medium Density, based on OnSemi component dimensions"
  rect 85x107.99 smd: 1(-87.01,0) 2(87.01,0)
  silkscreen extent -125,-79 125,79, body extent -104,-73 104,73, height 89
SMC [mil] "Molded Diode, 2-Leads, Body 6.9x5.8mm, IPC Medium Density, based on OnSemi component dimensions and land patterns"
  rect 110x150 smd: 1(-140.49,0) 2(140.49,0)
  silkscreen extent -221,-124 189,123, body extent -156,-116 156,116, height 91
TI_Stacked_Overlay_Small [mil]
  silkscreen extent -418,-98 418,98
VCTA32251B [mm] "CYNTEC"
  rect 1.15x2.8 smd: 1(-1.175,0) 2(1.175,0)
  body extent -1.7,-1.35 1.7,1.35, height 1.21
WE-SL5_HC [mm] "SMD, 4-Leads, Body 9.5x8.3mm"
  rect 2.7x2.7 smd: 1(-3.8,3.1) 2(-3.8,-3.1) 3(3.8,-3.1) 4(3.8,3.1)
  silkscreen extent -5.2,-4.15 4.75,4.15, body extent -4.75,-4.15 4.75,4.15, height 5.31
WEEE_Minimum [mil] "WEEElie bin"
  silkscreen extent -95,-172 99,104

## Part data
1V1 1V8 3V3 3V3LDO 3V3SW 5V TP12 TP13 VIN1 VIN2: library part CMP-0055160-1, "Test Point, Multipurpose, Purple, TH", Color=Purple, Manufacturer=Keystone, Supplier Part Number 1=36-5129-ND
C1 C6 C7: library part CMP-0006844-4, "CAP, CERM, 1000 pF, 50 V, +/- 5%, X7R, AEC-Q200 Grade 1, 0603", Cap_Case=0603, Manufacturer=Kemet, Supplier Part Number 1=399-12989-1-ND, TempCo=X7R, Tolerance_%=5%, Value1=Unknown, Value2=50V, ValueDisplayed=1000pF
C2: library part CMP-0011204-2, "CAP, AL, 47 uF, 50 V, +/- 20%, 0.68 ohm, AEC-Q200 Grade 2, SMD", Cap_Case=6.3x5.8mm, Manufacturer=Panasonic, Supplier Part Number 1=PCE5023CT-ND, Tolerance_%=20%, Value1="0.68 ohm", Value2=50V, ValueDisplayed=47uF
C3: library part CMP-0080106-1, "CAP, CERM, 1 µF, 50 V,+/- 10%, X7R, AEC-Q200 Grade 1, 1206", Cap_Case=1206, Manufacturer="Taiyo Yuden", PartNumber=UMK316B7105KLHT, Supplier Part Number 1=587-3518-1-ND, TempCo=X7R, Tolerance_%=10%, Value2=50V, ValueDisplayed=1µF
C4: library part CMP-0008702-2, "CAP, CERM, 4.7 uF, 50 V, +/- 10%, X7R, 1206", Cap_Case=1206_180, Manufacturer=TDK, PartNumber=C3216X7R1H475K160AC, Supplier Part Number 1=445-8032-1-ND, TempCo=X7R, Tolerance_%=10%, Value1="0.003158 ohm", Value2=50V, ValueDisplayed=4.7uF
C5 C9: library part CMP-0007434-2, "CAP, CERM, 0.1 uF, 50 V, +/- 10%, X7R, 0603", Cap_Case=0603, Manufacturer=MuRata, Supplier Part Number 1=490-1519-1-ND, TempCo=X7R, Tolerance_%=10%, Value1=Unknown, Value2=50V, ValueDisplayed=0.1uF
C8: library part CMP-0009163-2, "CAP, CERM, 4.7 uF, 50 V, +/- 20%, X7R, AEC-Q200 Grade 1, 1210", Cap_Case=1210, Manufacturer=TDK, PartNumber=CGA6P3X7R1H475M250AB, Supplier Part Number 1=445-13030-1-ND, TempCo=X7R, Tolerance_%=20%, Value1=Unknown, Value2=50V, ValueDisplayed=4.7uF
C10 C20 C36: library part CMP-0080703-2, "CAP, CERM, 390 pF, 50 V,+/- 10%, X7R, AEC-Q200 Grade 1, 0402", Cap_Case=0402, Manufacturer=MuRata, Supplier Part Number 1=81-GCM155R71H391KA7D, TempCo=X7R, Tolerance_%=10%, Value2=50V, ValueDisplayed=390pF
C11 C21: library part CMP-0006293-1, "CAP, CERM, 0.22 uF, 16 V, +/- 10%, X7R, 0402", Cap_Case=0402, Manufacturer=TDK, Supplier Part Number 1=445-5936-1-ND, TempCo=X7R, Tolerance_%=10%, Value1=Unknown, Value2=16V, ValueDisplayed=0.22uF
C12 C13 C22 C23: library part CMP-0009162-2, "CAP, CERM, 4.7 uF, 50 V, +/- 10%, X7R, AEC-Q200 Grade 1, 1210", Cap_Case=1210_280, Manufacturer=TDK, Supplier Part Number 1=445-6999-1-ND, TempCo=X7R, Tolerance_%=10%, Value1="0.003166 ohm", Value2=50V, ValueDisplayed=4.7uF
C14 C24: library part CMP-0079602-1, "CAP, CERM, 0.1 µF, 50 V,+/- 10%, X7R, AEC-Q200 Grade 1, 0603", Cap_Case=0603, Manufacturer=Kemet, PartNumber=C0603C104K5RACAUTO, Supplier Part Number 1=399-6856-1-ND, TempCo=X7R, Tolerance_%=10%, Value2=50V, ValueDisplayed=0.1µF
C15 C16 C25 C26 C27 C29: library part CMP-0008811-1, "CAP, CERM, 22 uF, 10 V, +/- 10%, X7R, AEC-Q200 Grade 1, 1206", Cap_Case=1206, Manufacturer=MuRata, TempCo=X7R, Tolerance_%=10%, Value1=Unknown, Value2=10V, ValueDisplayed=22uF
C17 C28 C37: library part CMP-0006350-2, "CAP, CERM, 0.1 uF, 10 V, +/- 10%, X7R, AEC-Q200 Grade 1, 0402", Cap_Case=0402, Manufacturer=MuRata, Supplier Part Number 1=81-GCM155R71A104K5D, TempCo=X7R, Tolerance_%=10%, Value1=Unknown, Value2=10V, ValueDisplayed=0.1uF
C18 C19 C30 C33 C34 C35: library part CMP-0006349-1, "CAP, CERM, 1 uF, 10 V, +/- 10%, X7S, AEC-Q200 Grade 1, 0402", Cap_Case=0402, Manufacturer=MuRata, Supplier Part Number 1=81-GCM155C71A105KE8D, TempCo=X7S, Tolerance_%=10%, Value1=Unknown, Value2=10V, ValueDisplayed=1uF
C31 C32: library part CMP-0006639-2, "CAP, CERM, 0.01 uF, 16 V, +/- 10%, X7R, 0402", Cap_Case=0402, Manufacturer=MuRata, Supplier Part Number 1=490-1313-1-ND, TempCo=X7R, Tolerance_%=10%, Value1=Unknown, Value2=16V, ValueDisplayed=0.01uF
D1: library part CMP-0028936-2, "Diode, Schottky, 40 V, 4 A, AEC-Q101, SMC", Manufacturer=Vishay-Semiconductor, Value1=4A, Value2=0.44V
D2: library part CMP-0006049-2, "Diode, TVS, Bi, 36 V, 76 Vc, AEC-Q101, SMB", Manufacturer=STMicroelectronics, Supplier Part Number 1=497-12193-1-ND, Value1=W
FID1 FID2 FID3: library part CMP-0077181-1, "Fiducial mark.  There is nothing to buy or mount.", Manufacturer=N/A
GND GNDS GNDS1: library part CMP-0055148-1, "Test Point, Multipurpose, Black, TH", Color=Black, Manufacturer=Keystone, Supplier Part Number 1=36-5011-ND
H1 H2 H3 H4: library part CMP-0003617-1, "Machine Screw, Round, #4-40 x 1/4, Nylon, Philips panhead", Manufacturer="B&F Fastener Supply", Supplier Part Number 1=H542-ND
H5 H6 H7 H8: library part CMP-0003610-1, "Standoff, Hex, 0.5\"L #4-40 Nylon", Manufacturer=Keystone, Supplier Part Number 1=36-1902C-ND
J1: library part CMP-0055167-2, "Standard Banana Jack, Insulated, Red", Manufacturer=Keystone, Supplier Part Number 1=36-6091-ND
J2: library part CMP-0055168-2, "Standard Banana Jack, Insulated, Black", Manufacturer=Keystone, Supplier Part Number 1=36-6092-ND
J3 J4 J5 J6 J7 J8 J9 J10 J11: library part CMP-0002337-1, "Header, 100mil, 2x1, Tin, TH", Color=Black, Current_A=3A, Manufacturer="Sullins Connector Solutions", Supplier Part Number 1=S1012E-02-ND, Voltage_V=1.8kV
L1: library part CMP-0003374-1, "Ferrite Bead, 600 ohm @ 100 MHz, 3 A, 1210", Manufacturer="Taiyo Yuden", PartNumber=FBMH3225HM601NT, Supplier Part Number 1=587-1755-1-ND, Value1="0.042 ohm", Value2=3A, ValueDisplayed="600 ohm"
L2: library part CMP-0086569-1, "WE-MAIA SMD Power Inductor", Manufacturer="Wurth Electronics"
L3: library part CMP-0076872-1, "Coupled inductor, 11 µH, 2.5 A, 0.03 ohm, SMD", Manufacturer="Wurth Elektronik", Supplier Part Number 1=732-2960-1-ND, ValueDisplayed=11µH
L4: library part CMP-0059974-1, "Inductor, 3.3 uH, 2 A, 0.127 ohm, SMD", Manufacturer=Cyntec, Value1="0.127 ohm", Value2=2A, ValueDisplayed=3.3uH
L5: library part CMP-0059972-1, "Inductor, 1.5 uH, 3.1 A, 0.054 ohm, SMD", Manufacturer=Cyntec, Value1="0.054 ohm", Value2=3.1A, ValueDisplayed=1.5uH
L6: library part CMP-0080779-1, "Inductor, Shielded, Metal Composite, 470 nH, 4.5 A, 0.026 ohm, SMD", Manufacturer=MuRata, PartNumber=DFE201612E-R47M{}P2, Value1="0.026 ohm", Value2=4.5A, ValueDisplayed=470nH
LBL1: library part CMP-0003625-1, "Thermal Transfer Printable Labels, 0.650\" W x 0.200\" H - 10,000 per roll", Manufacturer=Brady, Supplier Part Number 1=97C5133
Logo1: library part CMP-0074844-1
Logo2: library part CMP-0074838-1, "Texas Instrument Corporate Signature"
Logo3: library part CMP-0074847-1, "FCC_disclaimer"
Logo4: library part CMP-0074769-1
NT1 NT2 NT3 NT4 NT5 NT6 NT7 NT8: library part CMP-0078142-1, "Single point connection between nets.", Manufacturer=N/A
R1: library part CMP-0022717-2, "RES, 0.51, 1%, 0.1 W, AEC-Q200 Grade 1, 0603", Manufacturer=Panasonic, PartNumber=ERJ-3RQFR51V, Power_W=100mW, Supplier Part Number 1=P.51AJCT-ND, TempCo="300 ppm/C", Tolerance_%=1%, Value2=0.1W, Value_Code=R510, ValueDisplayed=0.51
R2 R8: library part CMP-0020720-3, "RES, 3.0, 5%, 0.125 W, AEC-Q200 Grade 0, 0805", Manufacturer=Panasonic, Power_W=125mW, Supplier Part Number 1=P3.0ACT-ND, TempCo="600 ppm/C", Tolerance_%=5%, Value2=0.125W, Value_Code=3R00, ValueDisplayed=3.0
R3 R5 R9 R12: library part CMP-0081856-1, "RES, 0, 0%, 0.2 W, AEC-Q200 Grade 0, 0402", Manufacturer=Vishay-Dale, Power_W=200mW, Supplier Part Number 1=541-0.0YBTR-ND, Tolerance_%=0%, Value2=0.2W, Value_Code=0
R4 R6 R7 R10 R13 R14 R16 R17 R18 R19 R20 R21: library part CMP-0026753-1, "RES, 100 k, 1%, 0.063 W, AEC-Q200 Grade 0, 0402", Manufacturer="Stackpole Electronics Inc", Power_W=63mW, Supplier Part Number 1=RMCF0402FT100KCT-ND, TempCo="100 ppm/C", Tolerance_%=1%, Value2=0.063W, Value_Code=100k
R11: library part CMP-0026319-2, "RES, 37.4 k, 1%, 0.063 W, AEC-Q200 Grade 0, 0402", Manufacturer=Vishay-Dale, Power_W=63mW, Supplier Part Number 1=541-37.4KLCT-ND, TempCo="100 ppm/C", Tolerance_%=1%, Value2=0.063W, Value_Code=37k4, ValueDisplayed=37.4k
R15: library part CMP-0025950-3, "RES, 100 k, 1%, 0.063 W, AEC-Q200 Grade 0, 0402", Manufacturer=Vishay-Dale, Power_W=63mW, Supplier Part Number 1=541-100KLCT-ND, TempCo="100 ppm/C", Tolerance_%=1%, Value2=0.063W, Value_Code=100k
U1: library part CMP-0750138-1, "3.5-V to 36-V, 1.5-A Synchronous Step-Down Voltage Regulator with Spread Spectrum, PWP0016K (HTSSOP-16)", Alternate Manufacturer="Texas Instruments"
U2: library part CMP-0860155-1, "Automotive capacitor-free 300-mA LDO regulator with foldback current limit for portable devices, DBV0005A (SOT-23-5)", Alternate Manufacturer="Texas Instruments", Operating Temperature Range="-40 to 125,-40 to 150 C", Rating=Automotive
U3: library part CMP-0080080-4, "3.5-V to 36-V, 2.5-A Synchronous Step-Down Voltage Regulator with Spread Spectrum, PWP0016D (TSSOP-16)", Alternate Manufacturer="Texas Instruments", Rating=Automotive
U4: library part CMP-0067085-2, "3A, 6V input, up to 97% efficiency, Synchronous Step Down Converter with DCS(TM) Control, RGT0016C (VQFN-16)", Alternate Manufacturer="Texas Instruments", Alternate PartNumber=TPS62090RGTT
U5: library part CMP-0081996-1, "5.5V, 2A, 52mO Automotive High-Side Load Switch with Adjustable Rise Time & Quick Output Discharge, DBV0006A (SOT-23-6)", Alternate Manufacturer="Texas Instruments", Alternate PartNumber=TPS22918TDBVTQ1, Operating Temperature Range="-40 to 105 C", Rating=Automotive
U6: library part CMP-0076265-4, "Automotive 500-mA Low-Noise, Low-IQ LDO, DRV0006A (WSON-6)", Alternate Manufacturer="Texas Instruments", Alternate PartNumber=LP5912Q1.8DRVTQ1
U7: library part CMP-0013379-4, "High-Accuracy Voltage Supervisor With Integrated Watchdog Timer, DRB0008A (VSON-8)", Alternate Manufacturer="Texas Instruments", Alternate PartNumber=TPS3851G18EDRBT, Operating Temperature Range="-40 to 125 C", Rating=Catalog
ZZ1: library part CMP-0003616-3
ZZ2: library part CMP-0077236-1
ZZ3: library part CMP-0077237-1
ZZ4: library part CMP-0077238-1

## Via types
v1: diameter 20, hole 8, Top Layer to Bottom Layer, tented both sides, 121 vias
v2: diameter 19.68, hole 7.87, Top Layer to Bottom Layer, 23 vias
v3: diameter 19.68, hole 7.87, Top Layer to Bottom Layer, tented both sides, 12 vias

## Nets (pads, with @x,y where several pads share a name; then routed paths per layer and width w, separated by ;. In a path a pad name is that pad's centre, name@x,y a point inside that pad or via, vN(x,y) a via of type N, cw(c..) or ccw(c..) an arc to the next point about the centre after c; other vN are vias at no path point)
1V1: C29.1 J6.1 L6.2 NT6.1 R11.2 U4.16 | length 545.6
  Top Layer w9: U4.16@3064.53,2204.88 3064.53,2140.04 3109.57,2095 C29.1@3141.93,2095
  Top Layer w10: R11.2@3155,2365 v1(3180,2365)
  Top Layer w15: C29.1@3141.93,2095 C29.1@3161.93,2075
  Top Layer w40: C29.1@3161.93,2075 J6.1@3255,2075
  Bottom Layer w10: NT6.1@3171.68,2156 3156.65,2156 v1(3155,2154.35) 3155,2340 v1(3180,2365)
1V8: 1V8.1 C34.1 U6.1 | length 208.1
  Top Layer w10: U6.1@3208.39,2634.41 3222.98,2634.41 3237.39,2620 C34.1@3260,2620 3308.73,2620 3325,2603.73 1V8.1@3325,2525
